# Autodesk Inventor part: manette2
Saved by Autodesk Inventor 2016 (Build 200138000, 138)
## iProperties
Created: 2013-10
Part Number: manette2
Material: solidworks materials|ABS
Document SubType Name: Modeling
Designer: Bruno
Density: 1.02 g/cm^3
Appearance: 255,255,2551
Author: Bruno
Sending System: SolidWorks 2013
Last Author: christophe
Last Saved: 2014-02-15
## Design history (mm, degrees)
feature "Cut-Revolve2"
node "Solide1"
